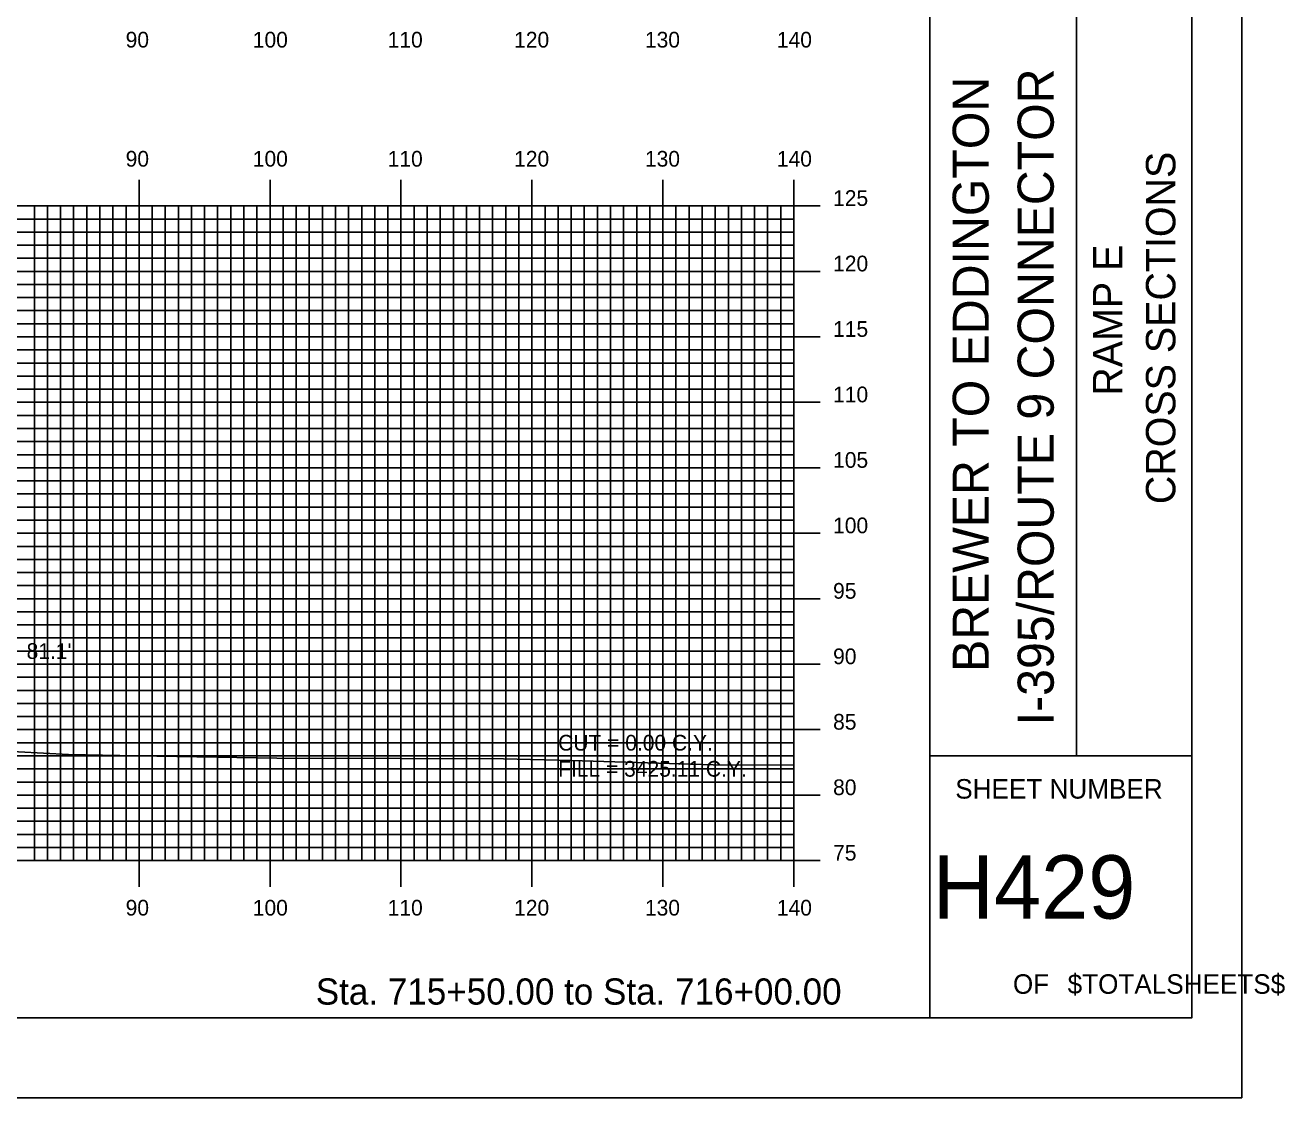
# Model space of a CAD drawing. Extents: x 856478 to 856821, y 364366 to 364586.
# Drawn here: x 856724.6 to 856820.8, y 364365.7 to 364447.6 of the extents above; entities that cross this region are included whole.
import ezdxf

# ---------------------------------------------------------------- set-up
doc = ezdxf.new("R2010")
doc.units = 0
for name, color, linetype in [('BORDER', 7, 'Continuous'), ('D_Text_Standard', 7, 'Continuous'), ('H_V ANNOTATION', 7, 'Continuous'), ('MAJOR', 7, 'Continuous'), ('MINOR', 7, 'Continuous'), ('PLOT BOUNDARY', 7, 'Continuous'), ('S_Roadway_Centerline', 7, 'Continuous')]:
    doc.layers.add(name, color=color, linetype=linetype)

msp = doc.modelspace()

# ---------------------------------------------------------------- linework, layer by layer
at = {"layer": 'BORDER'}
for p, q in [((856793.709, 364371.787), (856793.709, 364581.787)), ((856804.891, 364391.793), (856804.891, 364461.793)), ((856793.709, 364391.793), (856813.709, 364391.793))]:
    msp.add_line(p, q, dxfattribs=at)
msp.add_lwpolyline([(856493.709, 364371.787), (856813.709, 364371.787), (856813.709, 364581.787), (856493.709, 364581.787)], close=True, dxfattribs=at)
at = {"layer": 'MAJOR'}
for p, q in [((856733.309, 364435.791), (856733.309, 364433.787)), ((856743.309, 364435.791), (856743.309, 364433.787)), ((856753.309, 364435.791), (856753.309, 364433.787)), ((856763.309, 364435.791), (856763.309, 364433.787)), ((856773.309, 364435.791), (856773.309, 364433.787)), ((856783.309, 364435.791), (856783.309, 364433.787)), ((856503.309, 364433.787), (856783.309, 364433.787)), ((856503.309, 364433.787), (856783.309, 364433.787)), ((856733.309, 364383.787), (856733.309, 364433.787)), ((856743.309, 364383.787), (856743.309, 364433.787)), ((856753.309, 364383.787), (856753.309, 364433.787)), ((856763.309, 364383.787), (856763.309, 364433.787)), ((856773.309, 364383.787), (856773.309, 364433.787)), ((856785.313, 364433.787), (856781.305, 364433.787)), ((856783.309, 364383.787), (856783.309, 364433.787)), ((856783.309, 364383.787), (856783.309, 364433.787)), ((856503.309, 364428.787), (856783.309, 364428.787)), ((856785.313, 364428.787), (856781.305, 364428.787)), ((856503.309, 364423.787), (856783.309, 364423.787)), ((856785.313, 364423.787), (856781.305, 364423.787)), ((856503.309, 364418.787), (856783.309, 364418.787)), ((856785.313, 364418.787), (856781.305, 364418.787)), ((856503.309, 364413.787), (856783.309, 364413.787)), ((856785.313, 364413.787), (856781.305, 364413.787)), ((856503.309, 364408.787), (856783.309, 364408.787)), ((856785.313, 364408.787), (856781.305, 364408.787)), ((856503.309, 364403.787), (856783.309, 364403.787)), ((856785.313, 364403.787), (856781.305, 364403.787)), ((856503.309, 364398.787), (856783.309, 364398.787)), ((856785.313, 364398.787), (856781.305, 364398.787)), ((856503.309, 364393.787), (856783.309, 364393.787)), ((856785.313, 364393.787), (856781.305, 364393.787)), ((856503.309, 364388.787), (856783.309, 364388.787)), ((856785.313, 364388.787), (856781.305, 364388.787)), ((856503.309, 364383.787), (856783.309, 364383.787)), ((856503.309, 364383.787), (856783.309, 364383.787)), ((856733.309, 364381.783), (856733.309, 364383.787)), ((856743.309, 364381.783), (856743.309, 364383.787)), ((856753.309, 364381.783), (856753.309, 364383.787)), ((856763.309, 364381.783), (856763.309, 364383.787)), ((856773.309, 364381.783), (856773.309, 364383.787)), ((856785.313, 364383.787), (856781.305, 364383.787)), ((856783.309, 364381.783), (856783.309, 364383.787))]:
    msp.add_line(p, q, dxfattribs=at)
at = {"layer": 'MINOR'}
for p, q in [((856725.309, 364383.787), (856725.309, 364433.787)), ((856726.309, 364383.787), (856726.309, 364433.787)), ((856727.309, 364383.787), (856727.309, 364433.787)), ((856728.309, 364383.787), (856728.309, 364433.787)), ((856729.309, 364383.787), (856729.309, 364433.787)), ((856730.309, 364383.787), (856730.309, 364433.787)), ((856731.309, 364383.787), (856731.309, 364433.787)), ((856732.309, 364383.787), (856732.309, 364433.787)), ((856734.309, 364383.787), (856734.309, 364433.787)), ((856735.309, 364383.787), (856735.309, 364433.787)), ((856736.309, 364383.787), (856736.309, 364433.787)), ((856737.309, 364383.787), (856737.309, 364433.787)), ((856738.309, 364383.787), (856738.309, 364433.787)), ((856739.309, 364383.787), (856739.309, 364433.787)), ((856740.309, 364383.787), (856740.309, 364433.787)), ((856741.309, 364383.787), (856741.309, 364433.787)), ((856742.309, 364383.787), (856742.309, 364433.787)), ((856744.309, 364383.787), (856744.309, 364433.787)), ((856745.309, 364383.787), (856745.309, 364433.787)), ((856746.309, 364383.787), (856746.309, 364433.787)), ((856747.309, 364383.787), (856747.309, 364433.787)), ((856748.309, 364383.787), (856748.309, 364433.787)), ((856749.309, 364383.787), (856749.309, 364433.787)), ((856750.309, 364383.787), (856750.309, 364433.787)), ((856751.309, 364383.787), (856751.309, 364433.787)), ((856752.309, 364383.787), (856752.309, 364433.787)), ((856754.309, 364383.787), (856754.309, 364433.787)), ((856755.309, 364383.787), (856755.309, 364433.787)), ((856756.309, 364383.787), (856756.309, 364433.787)), ((856757.309, 364383.787), (856757.309, 364433.787)), ((856758.309, 364383.787), (856758.309, 364433.787)), ((856759.309, 364383.787), (856759.309, 364433.787)), ((856760.309, 364383.787), (856760.309, 364433.787)), ((856761.309, 364383.787), (856761.309, 364433.787)), ((856762.309, 364383.787), (856762.309, 364433.787)), ((856764.309, 364383.787), (856764.309, 364433.787)), ((856765.309, 364383.787), (856765.309, 364433.787)), ((856766.309, 364383.787), (856766.309, 364433.787)), ((856767.309, 364383.787), (856767.309, 364433.787)), ((856768.309, 364383.787), (856768.309, 364433.787)), ((856769.309, 364383.787), (856769.309, 364433.787)), ((856770.309, 364383.787), (856770.309, 364433.787)), ((856771.309, 364383.787), (856771.309, 364433.787)), ((856772.309, 364383.787), (856772.309, 364433.787)), ((856774.309, 364383.787), (856774.309, 364433.787)), ((856775.309, 364383.787), (856775.309, 364433.787)), ((856776.309, 364383.787), (856776.309, 364433.787)), ((856777.309, 364383.787), (856777.309, 364433.787)), ((856778.309, 364383.787), (856778.309, 364433.787)), ((856779.309, 364383.787), (856779.309, 364433.787)), ((856780.309, 364383.787), (856780.309, 364433.787)), ((856781.309, 364383.787), (856781.309, 364433.787)), ((856782.309, 364383.787), (856782.309, 364433.787)), ((856503.309, 364432.787), (856783.309, 364432.787)), ((856783.309, 364432.787), (856781.305, 364432.787)), ((856503.309, 364431.787), (856783.309, 364431.787)), ((856783.309, 364431.787), (856781.305, 364431.787)), ((856503.309, 364430.787), (856783.309, 364430.787)), ((856783.309, 364430.787), (856781.305, 364430.787)), ((856503.309, 364429.787), (856783.309, 364429.787)), ((856783.309, 364429.787), (856781.305, 364429.787)), ((856503.309, 364427.787), (856783.309, 364427.787)), ((856783.309, 364427.787), (856781.305, 364427.787)), ((856503.309, 364426.787), (856783.309, 364426.787)), ((856783.309, 364426.787), (856781.305, 364426.787)), ((856503.309, 364425.787), (856783.309, 364425.787)), ((856783.309, 364425.787), (856781.305, 364425.787)), ((856503.309, 364424.787), (856783.309, 364424.787)), ((856783.309, 364424.787), (856781.305, 364424.787)), ((856503.309, 364422.787), (856783.309, 364422.787)), ((856783.309, 364422.787), (856781.305, 364422.787)), ((856503.309, 364421.787), (856783.309, 364421.787)), ((856783.309, 364421.787), (856781.305, 364421.787)), ((856503.309, 364420.787), (856783.309, 364420.787)), ((856783.309, 364420.787), (856781.305, 364420.787)), ((856503.309, 364419.787), (856783.309, 364419.787)), ((856783.309, 364419.787), (856781.305, 364419.787)), ((856503.309, 364417.787), (856783.309, 364417.787)), ((856783.309, 364417.787), (856781.305, 364417.787)), ((856503.309, 364416.787), (856783.309, 364416.787)), ((856783.309, 364416.787), (856781.305, 364416.787)), ((856503.309, 364415.787), (856783.309, 364415.787)), ((856783.309, 364415.787), (856781.305, 364415.787)), ((856503.309, 364414.787), (856783.309, 364414.787)), ((856783.309, 364414.787), (856781.305, 364414.787)), ((856503.309, 364412.787), (856783.309, 364412.787)), ((856783.309, 364412.787), (856781.305, 364412.787)), ((856503.309, 364411.787), (856783.309, 364411.787)), ((856783.309, 364411.787), (856781.305, 364411.787)), ((856503.309, 364410.787), (856783.309, 364410.787)), ((856783.309, 364410.787), (856781.305, 364410.787)), ((856503.309, 364409.787), (856783.309, 364409.787)), ((856783.309, 364409.787), (856781.305, 364409.787)), ((856503.309, 364407.787), (856783.309, 364407.787)), ((856783.309, 364407.787), (856781.305, 364407.787)), ((856503.309, 364406.787), (856783.309, 364406.787)), ((856783.309, 364406.787), (856781.305, 364406.787)), ((856503.309, 364405.787), (856783.309, 364405.787)), ((856783.309, 364405.787), (856781.305, 364405.787)), ((856503.309, 364404.787), (856783.309, 364404.787)), ((856783.309, 364404.787), (856781.305, 364404.787)), ((856503.309, 364402.787), (856783.309, 364402.787)), ((856783.309, 364402.787), (856781.305, 364402.787)), ((856503.309, 364401.787), (856783.309, 364401.787)), ((856783.309, 364401.787), (856781.305, 364401.787)), ((856503.309, 364400.787), (856783.309, 364400.787)), ((856783.309, 364400.787), (856781.305, 364400.787)), ((856503.309, 364399.787), (856783.309, 364399.787)), ((856783.309, 364399.787), (856781.305, 364399.787)), ((856503.309, 364397.787), (856783.309, 364397.787)), ((856783.309, 364397.787), (856781.305, 364397.787)), ((856503.309, 364396.787), (856783.309, 364396.787)), ((856783.309, 364396.787), (856781.305, 364396.787)), ((856503.309, 364395.787), (856783.309, 364395.787)), ((856783.309, 364395.787), (856781.305, 364395.787)), ((856503.309, 364394.787), (856783.309, 364394.787)), ((856783.309, 364394.787), (856781.305, 364394.787)), ((856503.309, 364392.787), (856783.309, 364392.787)), ((856783.309, 364392.787), (856781.305, 364392.787)), ((856503.309, 364391.787), (856783.309, 364391.787)), ((856783.309, 364391.787), (856781.305, 364391.787)), ((856503.309, 364390.787), (856783.309, 364390.787)), ((856783.309, 364390.787), (856781.305, 364390.787)), ((856503.309, 364389.787), (856783.309, 364389.787)), ((856783.309, 364389.787), (856781.305, 364389.787)), ((856503.309, 364387.787), (856783.309, 364387.787)), ((856783.309, 364387.787), (856781.305, 364387.787)), ((856503.309, 364386.787), (856783.309, 364386.787)), ((856783.309, 364386.787), (856781.305, 364386.787)), ((856503.309, 364385.787), (856783.309, 364385.787)), ((856783.309, 364385.787), (856781.305, 364385.787)), ((856503.309, 364384.787), (856783.309, 364384.787)), ((856783.309, 364384.787), (856781.305, 364384.787))]:
    msp.add_line(p, q, dxfattribs=at)
at = {"layer": 'PLOT BOUNDARY'}
msp.add_lwpolyline([(856477.523, 364365.669), (856817.523, 364365.669), (856817.523, 364585.669), (856477.523, 364585.669)], close=True, dxfattribs=at)
at = {"layer": 'S_Roadway_Centerline'}
msp.add_lwpolyline([(856596.807, 364408.059), (856611.405, 364407.859), (856623.826, 364405.997), (856628.379, 364405.848), (856635.022, 364404.294), (856645.093, 364401.798), (856652.36, 364400.245), (856662.205, 364397.884), (856668.313, 364396.221), (856691.521, 364392.462), (856693.483, 364392.244), (856693.833, 364392.249), (856699.182, 364392.468), (856710.028, 364392.985), (856711.402, 364392.959), (856724.092, 364392.099), (856727.906, 364391.886), (856733.125, 364391.784), (856743.834, 364391.609), (856753.269, 364391.578), (856761.129, 364391.55), (856766.297, 364391.438), (856777.144, 364391.1), (856783.309, 364391.081)], dxfattribs=at)

# ---------------------------------------------------------------- texts
at = {"layer": 'BORDER'}
for s, height, p in [('I-395/ROUTE 9 CONNECTOR', 2.75575, (856803.158, 364394.117)), ('BREWER TO EDDINGTON', 2.75575, (856798.198, 364398.196)), ('CROSS SECTIONS', 2.25, (856812.45, 364411.009)), ('RAMP E', 2.25, (856808.4, 364419.291))]:
    msp.add_text(s, height=height, rotation=90, dxfattribs=at).set_placement(p)
for s, height, p in [('SHEET NUMBER', 1.49054, (856795.64, 364388.52)), ('H429', 4.8388, (856793.92, 364379.352)), ('OF', 1.4905, (856800.043, 364373.613)), ('$TOTALSHEETS$', 1.49054, (856804.222, 364373.613))]:
    msp.add_text(s, height=height, dxfattribs=at).set_placement(p)
at = {"layer": 'D_Text_Standard'}
for s, p in [("81.1'", (856724.717, 364399.189)), ('CUT = 0.00 C.Y.', (856765.309, 364392.187)), ('FILL = 3425.11 C.Y.', (856765.309, 364390.195))]:
    msp.add_text(s, height=1.2, dxfattribs=at).set_placement(p)
at = {"layer": 'H_V ANNOTATION'}
for s, height, p in [('90', 1.2, (856732.282, 364445.882)), ('100', 1.2, (856741.993, 364445.882)), ('110', 1.2, (856752.293, 364445.882)), ('120', 1.2, (856761.95, 364445.882)), ('130', 1.2, (856771.939, 364445.882)), ('140', 1.2, (856782.014, 364445.882)), ('90', 1.2, (856732.282, 364436.787)), ('100', 1.2, (856741.993, 364436.787)), ('110', 1.2, (856752.293, 364436.787)), ('120', 1.2, (856761.95, 364436.787)), ('130', 1.2, (856771.939, 364436.787)), ('140', 1.2, (856782.014, 364436.787)), ('125', 1.2, (856786.309, 364433.787)), ('120', 1.2, (856786.309, 364428.787)), ('115', 1.2, (856786.309, 364423.787)), ('110', 1.2, (856786.309, 364418.787)), ('105', 1.2, (856786.309, 364413.787)), ('100', 1.2, (856786.309, 364408.787)), ('95', 1.2, (856786.309, 364403.787)), ('90', 1.2, (856786.309, 364398.787)), ('85', 1.2, (856786.309, 364393.787)), ('80', 1.2, (856786.309, 364388.787)), ('75', 1.2, (856786.309, 364383.787)), ('90', 1.2, (856732.282, 364379.587)), ('100', 1.2, (856741.993, 364379.587)), ('110', 1.2, (856752.293, 364379.587)), ('120', 1.2, (856761.95, 364379.587)), ('130', 1.2, (856771.939, 364379.587)), ('140', 1.2, (856782.014, 364379.587)), ('Sta. 715+50.00 to Sta. 716+00.00', 2.0004, (856746.801, 364372.787))]:
    msp.add_text(s, height=height, dxfattribs=at).set_placement(p)

doc.saveas('drawing.dxf')
